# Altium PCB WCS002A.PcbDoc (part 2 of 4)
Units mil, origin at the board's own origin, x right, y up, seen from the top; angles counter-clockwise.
Board outline 2300 x 4058 mil, 4 copper layers (TOP, GND, PWR, BOTTOM), stack 28.8 mil thick; 311 components, 217 nets, 982 pads, 644 vias.
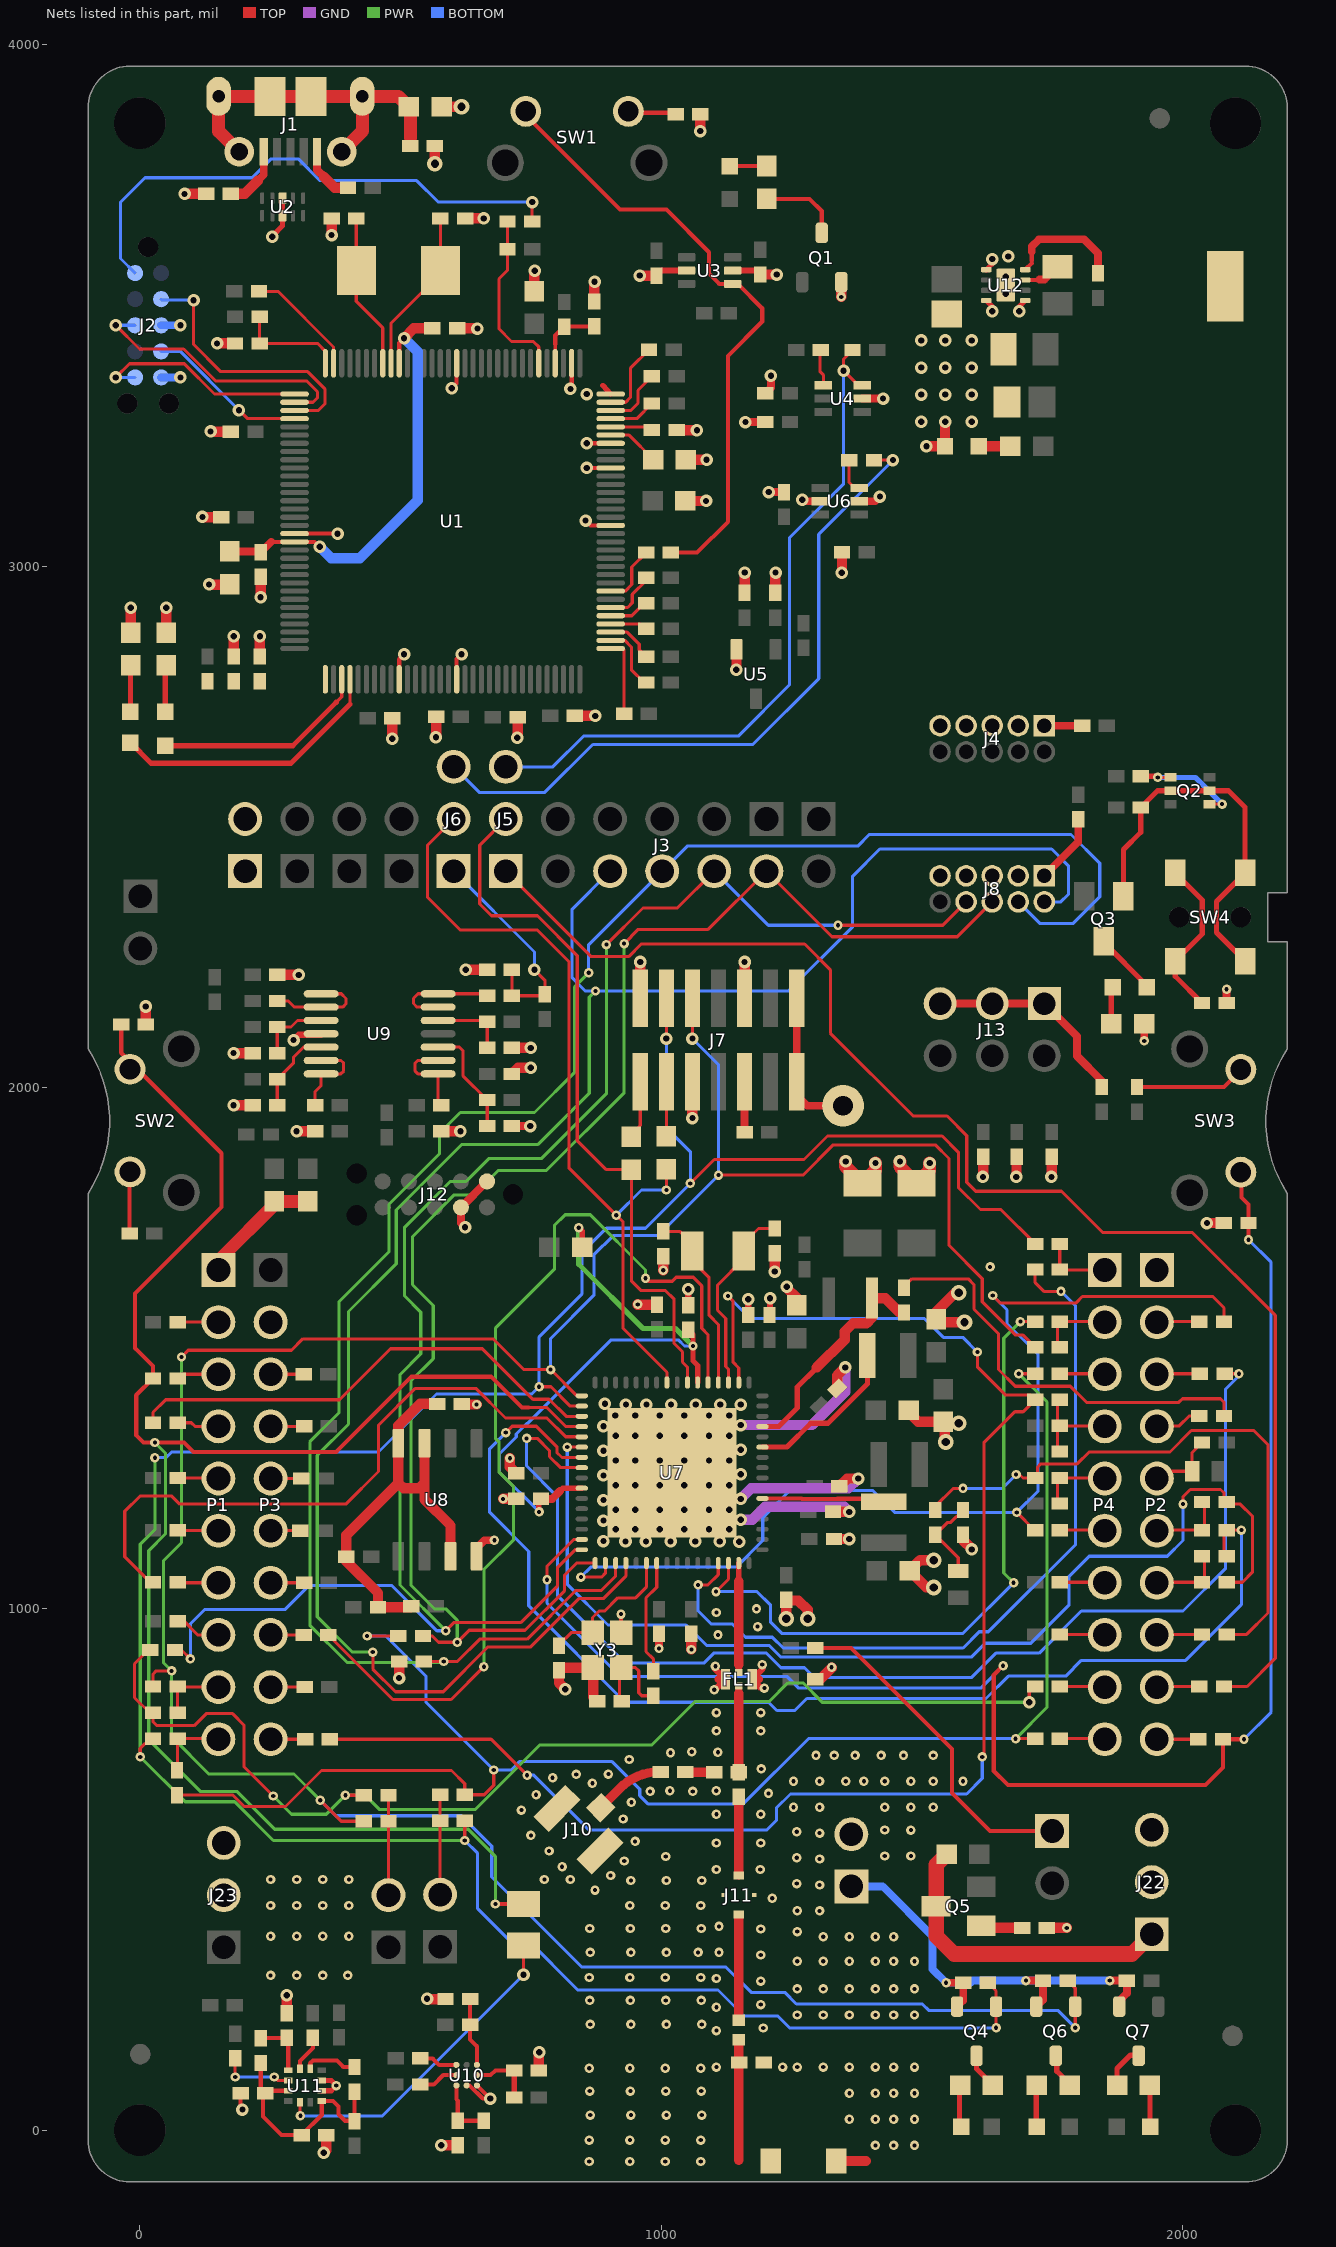
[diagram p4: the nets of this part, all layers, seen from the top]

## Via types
v1: diameter 18, hole 8, TOP to BOTTOM, tented both sides, 344 vias
v2: diameter 24, hole 12, TOP to BOTTOM, tented both sides, 244 vias
v3: diameter 24, hole 12.1, TOP to BOTTOM, 36 vias
v4: diameter 30, hole 16, TOP to BOTTOM, tented both sides, 18 vias
v5: diameter 24, hole 12.1, TOP to BOTTOM, tented top, 2 vias

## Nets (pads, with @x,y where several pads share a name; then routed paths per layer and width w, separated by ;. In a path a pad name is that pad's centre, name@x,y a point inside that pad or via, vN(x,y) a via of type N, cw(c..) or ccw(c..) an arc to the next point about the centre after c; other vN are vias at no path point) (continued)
FL_SWP: L7.2 R42.1 U7.45 | length 440.1
  TOP w10: U7.45@1194.02,1349.37 1225.28,1349.37 1260.79,1384.88 1260.79,1425.14 1298.43,1462.79
  TOP w19.9: 1298.43,1462.79 1351.79,1516.14 1351.79,1531.79 1367.79,1547.79 1393.79,1547.79 1404.13,1558.13 L7.2@1404.13,1595.79 1429.79,1595.79 1457.41,1568.17 R42.1@1465.79,1568.17
GND: C1.2 C2.2 C3.2 C4.2 C5.2 C6.1 C7.2 C8.2 C9.2 C10.2 C11.2 C12.2 C13.1 C14.2 C15.2 C16.2 C17.2 C18.2 C19.2 C20.2 C21.2 C22.2 C23.2 C24.2 C25.2 C27.2 C28.2 C29.2 C30.2 C31.2 C32.2 C33.2 C34.1 C34.2 C35.2 C36.2 C37.2 C38.2 C39.2 C40.2 C41.2 C42.2 C43.2 C44.2 C45.2 C46.2 C47.2 C48.2 C49.2 C50.2 C51.2 C52.2 C53.2 C54.2 C55.2 C56.2 C57.2 C58.2 C59.2 C60.2 C61.2 C62.2 C63.2 C64.2 D7.1 E1.1 E1.2 FL1.2 FL1.4 J2.3 J2.5 J4.3 J4.5 J4.7 J4.9 J7.5 J7.10 J7.13 J8.3 J8.5 J8.7 J8.9 J10.2 J10.3 J11.3 J11.4 J12.1 J12.9 J21.1 J21.2 J22.2 J22.3 J23.2 J23.3 J24.2 L2.2 L3.2 P2.1 P3.2 Q1.2 R11.1 R14.1 R16.1 R18.1 R19.1 R21.1 R23.1 R48.2 R49.2 R50.2 R51.2 R53.2 R106.1 R107.1 R114.1 R115.1 R126.1 R127.1 R128.1 R141.2 R142.2 R143.1 R144.1 R154.1 TP2.1 U1.10 U1.17 U1.48 U1.55 U1.58 U1.64 U1.66 U1.80 U1.114 U2.3 U2.8 U3.2 U3.5 U4.2 U5.2 U6.2 U6.5 U7.65 U8.4 U9.11 U10.A1 U10.A2 U11.8 U11.9 U12.1 U12.4 U12.5 U12.9 Y3.2 Y3.4 | length 6498.9
  TOP w7.5: U1.114@296.64,3062.17 v2(379.17,3062.17) ; v2(598.29,3340.79) 607.66,3350.16 U1.80@607.66,3388.94 ; U1.17@607.66,2782.64 607.66,2821.42 v2(617.03,2830.79) ; v2(854.79,3087.28) 864.16,3077.91 U1.48@902.94,3077.91
  TOP w8: C59.2@193.17,70.41 193.17,43.03 v2(196.79,39.41) ; U10.A2@626.79,85.72 632.28,85.72 657.59,60.41 v2(671.79,60.41) U10.A1@646.47,85.72 ; v2(856.88,3188.15) U1.55@902.94,3188.15 ; v2(856.88,3235.39) U1.58@902.94,3235.39 ; Y3.2@921.38,954.25 Y3.2@922.79,955.66 ; Y3.2@922.79,954.25 Y3.2@922.79,955.66 ; v1(922.79,989.79) Y3.2@922.79,955.66
  TOP w9: U1.10@497.43,2782.64 497.43,2821.42 v2(506.8,2830.79) ; v2(825.79,3339.79) 828.13,3342.13 U1.66@828.13,3388.94
  TOP w10: v2@254.29,3633.29 273.79,3652.79 U2.8@273.79,3672.06 U2.3@273.79,3705.52 ; U11.8@348.87,75.57 356.79,75.57 366.95,75.57 v1(376.79,85.41) 366.94,95.25 U11.9@348.87,95.25 ; 887.9,3346.1 U1.64@902.94,3329.96 ; U12.4@1623.39,3509.26 1634.79,3497.86 v2(1634.79,3488.79) ; U12.1@1623.39,3568.32 1634.79,3579.72 v2(1634.79,3588.79) ; v2(1686.79,3488.79) 1686.79,3497.86 U12.5@1698.19,3509.26
  TOP w12: v2(294.79,2090.79) 304.79,2100.79 U9.11@347.58,2100.79 ; C5.2@990.79,3557.17 1000.41,3566.79 U3.2@1048.5,3566.79 ; C28.2@1051.79,1582.41 v2(1051.79,1612.79) ; v1(1101.79,844.79) 1103.15,844.79 FL1.4@1123.15,864.79 1103.79,884.15 v1(1103.79,889.79) ; U3.5@1137.08,3566.79 1182.17,3566.79 C4.2@1189.79,3559.17 ; C46.2@1166.79,1563.41 v2(1166.79,1593.79) ; v1(1193.79,892.79) 1193.79,884.25 FL1.2@1174.33,864.79 1191.33,847.79 v1(1197.79,847.79) ; C36.2@1207.79,1563.41 1208.79,1564.41 v2(1208.79,1595.79)
  TOP w15: v2(623.79,1731.79) 615.79,1739.79 J12.9@615.79,1769.79 J12.1@665.79,1819.79 ; U8.4@645.79,1100.74 645.79,1115.99 661.1,1131.3 v1(679.9,1131.3) ; R114.1@713.41,1925.79 v2(748.79,1925.79) ; v1(995.79,923.79) C47.2@995.79,952.17 ; 1109.79,864.79 FL1.4@1123.15,864.79 ; v2(1161.39,3276.2) C14.2@1199.76,3276.2 ; FL1.2@1174.33,864.79 1187.79,864.79 ; C17.2@1199.76,3331.2 1210.39,3341.82 v2(1210.39,3365.2) ; v2(1206.39,3141.82) C24.2@1235.39,3141.82 ; v2(1270.39,3127.2) 1273.39,3124.2 U6.5@1304.98,3124.2 ; U6.2@1379.79,3124.2 1410.39,3124.2 v2(1419.39,3133.2) ; U4.2@1385.79,3321.2 v2(1425.39,3321.2) ; v1(1926.28,2089.28) R143.1@1926.28,2121.79 ; R144.1@2084.41,2161.79 v1(2084.41,2188.41)
  TOP w18: 1148.74,-58.07 L3.2@1148.74,172.5
  TOP w19.9: C53.2@263.41,2215.79 v2(304.79,2215.79) ; v2(624.79,2225.79) C54.2@666.17,2225.79 ; v1(696.79,1210.79) C32.2@722.17,1210.79 C32.2@726.5,1210.79 ; C50.2@803.79,882.17 803.79,857.79 v2(815.79,845.79) ; C50.2@803.79,886.5 Y3.4@868.23,886.5 ; Y3.4@869.37,886.5 869.37,831.2 877.17,823.41 C51.2@877.17,822.79 ; v1(1003.79,1649.12) C48.2@1003.79,1676.5 ; v1(1057.79,921.79) C38.2@1057.79,952.17 C38.2@1057.79,953.5 ; v2(1217.79,1646.79) C49.2@1217.79,1682.17 ; v2(1240.79,1617.79) 1240.79,1615.21 1259.79,1596.21 C45.2@1259.79,1582.28 ; C27.2@1295.41,864.79 1304.74,864.79 v1@1326.79,886.84 ; C29.2@1325.08,1185.79 C29.2@1329.41,1185.79 v2(1360.79,1185.79) ; C37.2@1331.41,1133.79 v2(1360.79,1133.79) ; C31.2@1334.43,1419.43 C31.2@1337.49,1422.49 1337.49,1447.49 v2(1352.79,1462.79) ; C30.2@1335.41,1235.79 C30.2@1337.56,1235.79 ; E1.2@1335.59,-59.21 1392.79,-59.21 ; C30.2@1341.41,1234.79 1356.41,1249.79 v2(1377.79,1249.79) ; v2@1509.77,3229.74 1509.82,3229.79 D7.1@1544.31,3229.79 v2@1544.29,3275 ; v4(1522.79,1040.79) 1508.28,1040.79 C35.2@1476.28,1072.79 1496.28,1092.79 v4(1522.79,1092.79) ; C40.2@1543.79,1355.29 1543.79,1321.79 v4(1545.79,1319.79) ; v4(1570.79,1605.79) 1563.79,1605.79 1527.79,1569.79 C42.2@1527.79,1555.28 1533.28,1549.79 v4(1581.79,1549.79) ; v2(2046.71,1739.79) R142.2@2079.17,1739.79
  TOP w20: R18.1@-17.21,2872.28 v2@-17.21,2919.79 ; R141.2@11.41,2120.79 v2(11.41,2155.17) ; R19.1@50.79,2872.28 v2@50.79,2919.79 ; v2(85.79,3713.79) L2.2@127.17,3713.79 ; v2@120.42,3093.79 C8.2@156.17,3093.79 ; v2@133.17,2964.28 C19.2@171.79,2964.28 ; v2@135.92,3257.79 C9.2@174.54,3257.79 ; v2(148,3427) C1.2@182.38,3427 ; v2(179.79,1965.79) R115.1@216.17,1965.79 ; v2(179.79,2065.79) R106.1@216.17,2065.79 ; R16.1@179.79,2826.41 v2@179.79,2865.03 ; C3.2@229.79,2826.41 v2@229.79,2865.03 ; v2@231.79,2940.54 C18.2@231.79,2979.17 ; R126.1@281.79,224.03 v2(281.79,258.79) ; v2(300.42,1915.79) C56.2@336.17,1915.79 ; v2(352.79,-43.59) 357.41,-38.97 C58.2@357.41,-9.59 ; v2(367.75,3634.8) C13.1@367.75,3666.61 ; v2@484.41,2669.17 C15.2@484.41,2707.79 ; v2@497.17,866.17 v2(497.17,866.98) R48.2@497.17,898.79 ; v2(550.79,251.79) 551.17,251.41 R127.1@586.17,251.41 ; v4(565.91,3771.91) C2.2@565.91,3805.79 ; v2@568.17,2672.17 C12.2@568.17,2710.79 ; v2@577.79,-29.59 578.17,-29.21 C57.2@609.79,-29.21 ; C55.2@578.41,1915.79 v2(614.79,1915.79) ; R14.1@578.78,3880.79 v4(616.79,3880.79) ; C20.2@608.41,3455.79 v2@647.03,3455.79 ; C33.2@617.28,1392.89 618.38,1391.79 v1(645.79,1391.79) ; C6.1@623.74,3666.7 v2(659.49,3666.7) ; v1(709.79,1288.79) 709.79,1272.17 C43.2@722.17,1259.79 ; C52.2@713.41,2025.79 725.41,2037.79 v2(749.79,2037.79) ; R107.1@713.41,2075.79 v2(749.79,2075.79) ; v2@724.41,2671.17 C16.2@724.41,2709.79 ; C10.2@756.79,3527.28 v2@756.79,3565.91 ; R128.1@765.41,114.41 765.41,149.03 v2(765.79,149.41) ; C7.2@834.41,2712.79 v2@873.03,2712.79 ; C23.2@871.79,3506.41 C23.2@871.79,3507.41 v2@871.79,3545.03 ; v1(954.79,1583.79) 955.17,1583.41 C44.2@991.79,1583.41 ; v2(958.98,3557.17) C5.2@990.79,3557.17 ; J7.13@959.79,2165.59 J7.13@959.79,2170.91 v2@959.79,2240.03 ; R11.1@1029.41,3260.79 v2@1068.03,3260.79 ; C11.2@1046.28,3124.79 v2(1085.97,3124.79) ; R23.1@1047.28,3203.79 v2(1086.97,3203.79) ; v2@1059.79,1941.55 J7.10@1059.79,2010.67 J7.10@1059.79,2015.98 ; v2(1075.03,3834.41) R21.1@1075.03,3866.79 ; v2@1144.39,2801.41 U5.2@1144.39,2840.03 ; J7.5@1159.79,2165.59 J7.5@1159.79,2170.91 v2@1159.79,2240.03 ; C21.2@1159.79,2948.41 v2@1159.79,2987.03 ; C4.2@1189.79,3559.17 v2(1221.6,3559.17) ; C22.2@1218.79,2948.41 v2@1218.79,2987.03 ; v4@1241.79,980.79 1239.79,982.79 C41.2@1239.79,1017.17 1241.17,1015.79 1262.79,1015.79 1280.79,997.79 v4(1280.79,980.79) ; v1(1345.19,3516.19) Q1.2@1345.19,3544.54 ; v2(1346.39,2987.2) 1346.76,2987.57 C25.2@1346.76,3026.2 ; C39.2@1477.28,1373.79 1492.78,1358.29 C40.2@1534.79,1358.29 ; C40.2@1543.79,1355.29 C40.2@1543.29,1355.79 ; v4(1570.79,1355.79) C40.2@1543.29,1355.79 ; R53.2@1578.79,1142.17 1578.79,1131.79 1595.79,1114.79 v2(1595.79,1113.79) ; v2@1617.41,1828.54 R51.2@1617.41,1867.17 ; v2@1681.41,1828.54 R50.2@1681.41,1867.17 ; R154.1@1739.41,387.79 v1(1777.79,387.79) ; v2@1748.79,1828.54 R49.2@1748.79,1867.17 ; C40.2@1534.79,1358.29 C40.2@1540.79,1358.29 C40.2@1543.29,1355.79 ; C40.2@1534.79,1358.29 1538.29,1354.79 1539.29,1355.79 C40.2@1543.29,1355.79
  TOP w25: v2(1353.79,1857.96) 1353.79,1847.87 C64.2@1385.79,1815.87 1410.79,1840.87 v2(1410.79,1854.96) ; v2(1457.79,1857.96) 1457.79,1847.87 C63.2@1489.79,1815.87 1514.79,1840.87 v2(1514.79,1854.96)
  GND w19.9: v2(1152.28,1170.91) 1174.91,1170.91 1199.74,1195.74 1350.84,1195.74 v2(1360.79,1185.79) ; v2(1152.49,1210.69) 1172.59,1230.79 1358.79,1230.79 v2(1377.79,1249.79) ; v2(1152.49,1352.42) 1289.04,1352.42 1352.79,1416.16 v2(1352.79,1462.79)
  BOTTOM w15: J2.5@40.79,3361.79 v2(77.79,3361.79) ; J2.3@40.79,3461.79 v2(77.79,3461.79)
  other v1: 861.79,-60.21 939.79,-60.21 1007.79,-60.21 1075.79,-60.21 1410.79,-29.21 1445.79,-29.21 1485.79,-29.21 861.79,-19.21 939.79,-19.21 1007.79,-19.21 1075.79,-19.21 1360.79,20.79 1410.79,20.79 1445.79,20.79 1485.79,20.79 863.79,28.79 941.79,28.79 1009.79,28.79 1077.79,28.79 1360.79,70.79 1410.79,70.79 1445.79,70.79 1485.79,70.79 862.79,74.79 940.79,74.79 1008.79,74.79 1076.79,74.79 861.79,118.79 939.79,118.79 1007.79,118.79 1075.79,118.79 1105.79,120.79 1232.79,120.79 1260.79,120.79 1310.79,120.79 1360.79,120.79 1410.79,120.79 1445.79,120.79 1485.79,120.79 1105.79,190.79 1195.79,195.79 863.79,202.79 941.79,202.79 1009.79,202.79 1077.79,202.79 1260.79,220.79 1310.79,220.79 1360.79,220.79 1410.79,220.79 1445.79,220.79 1485.79,220.79 1105.79,235.79 1190.79,240.79 862.79,248.79 940.79,248.79 1008.79,248.79 1076.79,248.79 1260.79,270.79 1310.79,270.79 1360.79,270.79 1410.79,270.79 1445.79,270.79 1485.79,270.79 1190.79,285.79 1105.79,290.79 861.79,292.79 939.79,292.79 1007.79,292.79 1075.79,292.79 250.79,296.79 300.79,296.79 350.79,296.79 398.79,296.79 1260.79,323.79 1310.79,323.79 1360.79,323.79 1410.79,323.79 1445.79,323.79 1485.79,323.79 1190.79,335.79 863.79,340.79 941.79,340.79 1009.79,340.79 1070.79,340.79 1110.79,340.79 1310.79,370.79 1360.79,370.79 1410.79,370.79 1445.79,370.79 250.79,371.79 300.79,371.79 350.79,371.79 400.79,371.79 1260.79,380.79 1190.79,385.79 862.79,386.79 940.79,386.79 1008.79,386.79 1076.79,386.79 1110.79,390.79 1260.79,420.79 1303.77,420.51 250.79,430.79 300.79,430.79 350.79,430.79 400.79,430.79 939.79,430.79 1007.79,430.79 1075.79,430.79 1212.79,444.79 872.89,460.27 1303.77,470.23 1259.79,472.79 941.79,478.79 1009.79,478.79 1077.79,478.79 250.79,480.79 300.79,480.79 350.79,480.79 400.79,480.79 775.79,480.79 825.79,480.79 902.89,488.27 1105.79,499.79 1189.79,499.79 809.89,505.27 928.89,516.27 1303.77,519.94 1259.79,522.51 1008.79,524.79 1428.77,525.82 1478.77,525.78 784.89,535.27 1105.79,550.79 1190.79,550.79 949.79,553.79 749.89,565.27 1303.77,569.66 1259.79,572.23 1428.77,575.54 1478.77,575.5 926.79,596.79 1105.79,605.79 1190.79,605.79 731.66,613.79 1253.77,619.38 1303.77,619.38 1428.77,619.42 1478.77,619.38 1521.75,619.38 942.66,628.79 759.89,643.27 1205.79,645.79 978.66,649.79 1060.28,649.69 1016.66,650.79 1105.66,650.79 867.89,665.27 1253.77,669.1 1303.77,669.1 1353.77,669.1 1388.77,669.1 1428.77,669.1 1478.77,669.1 1521.75,669.1 1578.77,669.1 791.66,675.79 836.89,682.27 898.66,682.79 1191.79,692.79 938.66,710.79 1296.75,718.82 1331.75,718.82 1371.75,718.82 1421.75,718.82 1464.73,718.82 1521.75,718.82 1017.66,723.79 1108.66,724.79 1058.66,725.79 1105.79,765.79 1190.79,765.79 1105.79,800.79 1190.79,800.79 1326.79,887.79 1108.79,949.79 1184.79,965.79 1105.79,992.79 1182.79,999.79 1630.79,1655.79
  other v2: 577.79,-29.21 931.44,1129.09 970.69,1129.09 1017.93,1129.09 1065.18,1129.09 1112.42,1129.09 1149.45,1128.55 889.09,1129.91 889.09,1169.16 889.09,1208.4 889.09,1255.64 1152.49,1257.93 889.09,1302.89 1152.49,1305.18 889.09,1350.13 932.27,1391.66 971.51,1391.66 1018.76,1391.66 1066,1391.66 1113.24,1391.66 1152.49,1391.66 892.03,1393.45 1617.03,1828.17 1681.03,1828.17 1748.41,1828.17 1059.79,1941.06 959.79,2240.51 1159.79,2240.51 484.03,2668.79 724.03,2670.79 567.79,2671.79 873.41,2712.41 1144.01,2801.03 180.17,2865.41 230.17,2865.41 -17.59,2920.17 50.41,2920.17 231.41,2940.17 132.79,2964.66 1160.17,2987.41 1219.17,2987.41 120.04,3094.17 1508.56,3229.79 135.54,3258.17 1068.41,3260.41 1498.79,3276.79 1544.79,3276.79 1595.79,3276.79 1498.79,3328.79 1544.79,3328.79 1595.79,3328.79 856.88,3329.88 1498.79,3380.79 1544.79,3380.79 1595.79,3380.79 1498.79,3432.79 1544.79,3432.79 1595.79,3432.79 647.41,3455.41 872.17,3545.41 757.17,3566.28 1665.79,3593.79 253.79,3631.79
  other v3: 912.68,1152.68 949.92,1152.68 997.17,1152.68 1044.41,1152.68 1091.65,1152.68 1130.69,1152.68 912.68,1189.92 949.92,1189.92 997.17,1189.92 1044.41,1189.92 1091.65,1189.92 1130.69,1189.92 912.68,1237.17 949.92,1237.17 997.17,1237.17 1044.41,1237.17 1091.65,1237.17 1130.69,1237.17 912.68,1284.41 949.92,1284.41 997.17,1284.41 1044.41,1284.41 1091.65,1284.41 1130.69,1284.41 912.68,1331.65 949.92,1331.65 997.17,1331.65 1044.41,1331.65 1091.65,1331.65 1130.69,1331.65 911.69,1370.69 949.92,1370.69 997.17,1370.69 1044.41,1370.69 1091.65,1370.69 1130.69,1370.69
  other v4: 1239.79,980.79
  other v5: 1660.6,3522.3 1660.79,3555
IRSTN: J2.10 R22.1 | length 1043.4
  TOP w6: R22.1@752.41,3660.79 v2(752.41,3698.17)
  BOTTOM w6: J2.10@-9.21,3561.79 -37.21,3589.79 -37.21,3697.79 9.79,3744.79 215.79,3744.79 252,3781 303.8,3781 345.5,3739.3 530.8,3739.3 571.93,3698.17 v2(752.41,3698.17)
ITCK: J2.4 U1.100 | length 309.3
  TOP w6: v2(190,3299) 190.57,3299 206.94,3282.64 U1.100@296.64,3282.64
  BOTTOM w6: J2.4@40.79,3411.79 77.21,3411.79 v2(190,3299)
ITDI: J2.8 U1.98 | length 535.9
  TOP w6: v2(-46.21,3461.79) -0.63,3416.2 83.8,3416.2 145.21,3354.79 319.99,3354.79 340.79,3333.99 340.79,3322.79 332.13,3314.13 U1.98@296.64,3314.13
  BOTTOM w6: v2(-46.21,3461.79) J2.8@-9.21,3461.79
ITDO: J2.6 U1.97 | length 412.4
  TOP w6: v2(-46.21,3361.79) -20,3388 85,3388 143.12,3329.88 U1.97@294.29,3329.88
  BOTTOM w6: v2(-46.21,3361.79) J2.6@-9.21,3361.79
ITMS: J2.2 U1.99 | length 527.3
  TOP w6: v2(103,3510) 103,3425 155.21,3372.79 321.79,3372.79 354.79,3339.79 354.79,3310.79 342.39,3298.39 U1.99@296.64,3298.39
  BOTTOM w6: J2.2@40.79,3511.79 42.57,3510 v2(103,3510)
LED0: D2.2 U1.3 | length 412.2
  TOP w6: 375.79,2737.79 387.19,2749.19 U1.3@387.19,2782.64
  TOP w10: D2.2@48.79,2655.31 293.31,2655.31 376.79,2738.79
LED1: D1.1 U1.4 | length 532.1
  TOP w6: 402.94,2734.94 U1.4@402.94,2782.64
  TOP w10: D1.1@-18.21,2661.26 21.26,2621.79 289.79,2621.79 402.94,2734.94
LP_GPIO_01: J5.1 R82.2 | length 2751
  TOP w6: J5.1@701.79,2414.79 865.79,2250.79 937.54,2250.79 961.75,2275 1275,2275 1324.5,2225.5 1324.5,2104.07 1483.37,1945.2 1548.37,1945.2 1586,1907.57 1586,1818 1603.21,1800.79 1767.79,1800.79 1846.79,1721.79 2018.79,1721.79 2177.79,1562.79 2177.79,904.79 2123.79,850.79 R82.2@2079.68,850.79
LP_GPIO_02: C54.1 J6.1 R101.2 R105.2 | length 423.3
  TOP w6: C54.1@713.41,2225.79 R105.2@713.41,2175.79 774.17,2175.79 R101.2@776.79,2178.41 776.79,2205.79 v2(756.79,2225.79)
  BOTTOM w6: J6.1@601.79,2414.79 756.79,2259.79 v2(756.79,2225.79)
LP_RESET_OUT: D5.2 P2.5 R136.2 | length 134.8
  TOP w6: P2.5@1952.06,1249.78 1966.06,1263.79 D5.2@2018.2,1263.79 2018.2,1299.82 R136.2@2037.17,1318.79
NetC1_1: C1.1 R13.2 U1.96 | length 206.3
  TOP w6: R13.2@229.62,3478 C1.1@229.62,3427 340.57,3427 355.69,3411.88 U1.96@355.69,3388.94
NetC2_1: C2.1 J1.6 J1.7 J1.8 J1.9 J1.10 J1.11 R14.2 | length 694.7
  TOP w22: C2.1@518.66,3805.79 518.66,3820.66
  TOP w25: J1.10@190.36,3794.64 151.21,3833.79 150.99,3833.79 J1.9@150.99,3900.94 J1.8@249.42,3900.94 J1.7@328.16,3900.94 J1.6@426.58,3900.94 ; J1.11@387.21,3794.64 426.58,3834.01 J1.6@426.58,3900.94 ; 518.66,3820.66 518.66,3877.91 R14.2@515.79,3880.79 495.64,3900.94 J1.6@426.58,3900.94
NetC3_1: C3.1 R15.2 R16.2 U1.1
NetC6_2: C6.2 U1.88 Y1.2 | length 317
  TOP w6: U1.88@481.68,3388.94 481.68,3465.68 576.5,3560.5 Y1.2@576.5,3566.79 C6.2@576.5,3666.7
NetC13_2: C13.2 U1.89 Y1.1 | length 298.8
  TOP w6: C13.2@415.08,3666.7 Y1.1@415.08,3566.79 415.08,3507.64 465.93,3456.79 U1.89@465.93,3388.94
NetC18_1: C18.1 C19.1 C20.1 U1.87 U1.115 | length 858.7
  TOP w7.5: 252.04,3046.42 U1.115@296.64,3046.42 335.42,3046.42 v2(344.79,3037.05)
  TOP w9: U1.87@497.43,3388.94 497.43,3427.72 v2(506.8,3437.09)
  TOP w15: C19.1@177.79,3030.29 179.91,3028.17 233.54,3028.17 251.8,3046.42 252.04,3046.42
  TOP w20: v2(506.8,3437.09) 525.5,3455.79 C20.1@561.17,3455.79
  BOTTOM w20: v2(344.79,3037.05) 367.05,3014.79 421.79,3014.79 532.79,3125.79 532.79,3411.09 v2(506.8,3437.09)
NetC23_1: C23.1 R28.2 U1.68 | length 135.3
  TOP w7.5: U1.68@796.64,3388.94 796.64,3425.64
  TOP w8: 796.64,3425.64 796.64,3442.02 R28.2@813.79,3459.17 C23.1@871.79,3459.17
NetC26_1: C26.1 R37.2 | length 55.5
  TOP w18: C26.1@1046.03,686.41 R37.2@1101.54,686.41
NetC26_2: C26.2 J10.1 | length 136.9
  TOP w18: J10.1@883.89,618.71 920.82,655.64 cw(c998.2,578.25) C26.2@984.56,686.84 ; C26.2@986.38,687.05 C26.2@998.78,687.05
NetC28_1: C28.1 C32.1 R36.1 U7.10 U7.54 | length 1231.8
  TOP w10: C32.1@765.08,1210.79 765.08,1186.5 v1(765.79,1185.79) ; 805.79,1225.79 811.26,1231.26 U7.10@847.56,1231.26 ; v1(841.79,1730.79) 848.28,1724.29 R36.1@848.28,1693.79 ; C28.1@1051.79,1535.17 1060.79,1526.17 1060.79,1475.67 1070,1466.46 U7.54@1070,1434.02
  TOP w15: C32.1@765.08,1210.79 C32.1@769.41,1210.79 790.79,1210.79 805.79,1225.79
  PWR w10: v1(841.79,1730.79) 841.79,1660.79 964.79,1537.79 1027.21,1537.79 v1(1061,1504)
  BOTTOM w6: v1(765.79,1185.79) 689.79,1261.79 689.79,1297.5 721.79,1329.5 721.79,1335.07 741.5,1354.79 742.87,1354.79 903.87,1515.79 1032.79,1515.79 1044.57,1504 v1(1061,1504)
NetC33_1: C33.1 R38.1 R39.1 R41.1 U8.3 U8.7 U8.8 | length 836.9
  TOP w19.9: R39.1@519.54,1005.79 R39.1@520.54,1004.79 518.54,1002.79 R38.1@456.71,1002.79 456.71,1030.29 396.79,1090.21 396.79,1090.79 396.17,1091.41 R41.1@396.17,1099.79 395.79,1100.17 395.79,1130.22 396.11,1130.54 396.11,1141.11 495.79,1240.79 ; U8.7@545.79,1307.28 545.79,1240.79 ; C33.1@566.5,1392.89 537.89,1392.89 495.79,1350.79 495.79,1240.79 ; U8.3@595.79,1118.3 595.79,1159.79 545.79,1209.79 545.79,1240.79 ; 495.79,1240.79 505.79,1230.79 535.79,1230.79 545.79,1240.79
NetC48_1: C48.1 U7.52 Y2.2 | length 352.2
  TOP w6: C48.1@1003.79,1723.74 1035.26,1723.74 1059.57,1699.43 Y2.2@1059.57,1685.79 1059.57,1667 1091.79,1634.79 1091.79,1562.79 1109.79,1544.79 1109.79,1434.41 U7.52@1109.37,1434.02
NetC49_1: C49.1 U7.51 Y2.1 | length 368.2
  TOP w6: U7.51@1129.05,1434.02 1129.08,1459.49 1123.79,1464.79 1123.79,1556.79 1107.79,1572.79 1107.79,1620.79 1158,1671 1158,1701 1186.41,1729.41 C49.1@1217.79,1729.41
NetC50_1: C50.1 U7.22 Y3.3 | length 278
  TOP w6: C50.1@803.79,929.41 803.79,930.79 827.25,954.25 Y3.3@868.23,954.25 868.23,983.23 880.79,995.79 891.79,995.79 916.79,1020.79 950.79,1020.79 971.58,1041.58 U7.22@971.57,1087.56
NetC51_1: C51.1 R44.1 Y3.1 | length 180
  TOP w6: C51.1@920.08,817.79 Y3.1@920.08,886.02 ; Y3.1@920.08,887.32 950.25,887.32 956.81,880.76 956.81,838.76 962.41,833.17 R44.1@984.79,833.17
NetC57_1: C57.1 R116.1 U10.A3 | length 118.5
  TOP w8: U10.A3@607.1,85.72 607.1,59.09 609.79,56.41 C57.1@609.79,18.03 659.01,18.03 R116.1@659.31,18.34
NetC58_1: C58.1 C59.1 R117.1 R122.2 R132.2 U11.3 U11.7 | length 468
  TOP w8: R122.2@231.79,128.79 231.79,79.03 C59.1@240.41,70.41 ; U11.3@284.7,75.57 245.57,75.57 C59.1@240.41,70.41 ; R132.2@411.79,73.79 411.79,18.03 393.17,18.03 380.79,30.41 380.79,45.41 370.31,55.88 U11.7@348.87,55.88 348.87,29.12 C58.1@310.17,-9.59 271.79,-9.59 236.08,26.12 236.08,66.08 C59.1@240.41,70.41
NetD1_2: D1.2 R18.2 | length 89.4
  TOP w10: D1.2@-18.21,2720.31 -18.21,2808.29 R18.2@-17.21,2809.29
NetD2_1: D2.1 R19.2 | length 89.9
  TOP w10: D2.1@48.79,2720.27 48.79,2807.29 R19.2@50.79,2809.29
NetD3_1: D3.1 R24.2 | length 71
  TOP w8: D3.1@1131.79,3766.98 R24.2@1202.79,3766.98
NetD4_1: D4.1 R52.1 R53.1 | length 160.6
  TOP w6: D4.1@1569.79,1072.38 1569.79,1098.17 R52.1@1525.79,1142.17 1549.41,1165.79 1555.17,1165.79 R53.1@1578.79,1189.41
NetD6_1: D6.1 R143.2 | length 71.2
  TOP w10: R143.2@1863.29,2121.79 1863.29,2188.77 D6.1@1866.31,2191.79
NetD6_2: D6.2 Q3.3 | length 122.5
  TOP w10: Q3.3@1848.99,2280.21 1848.99,2277.81 1931.27,2195.53 D6.2@1931.27,2191.79
NetD7_2: D7.2 R145.2 | length 49.5
  TOP w20: D7.2@1610.27,3229.79 R145.2@1659.8,3229.79
NetD8_2: D8.2 R148.2 | length 88
  TOP w10: D8.2@1572.29,6.79 R148.2@1572.29,94.79
NetD9_1: D9.1 R147.2 | length 88
  TOP w10: D9.1@1719.29,6.79 R147.2@1719.29,94.79
NetD10_1: D10.1 R149.2 | length 88.4
  TOP w10: R149.2@1937.28,94.79 1937.28,7.79 D10.1@1938.27,6.79
NetFL1_1: FL1.1 U7.31 | length 209.9
  TOP w10: 1148.74,1052.79 U7.31@1148.74,1083.62 ; U7.31@1148.77,1083.65 U7.31@1148.74,1087.56
  TOP w12: FL1.1@1148.74,877.58 1148.74,892.79
  TOP w18: 1148.74,892.79 1148.74,1052.79
NetFL1_3: FL1.3 R37.1 R40.1 | length 164
  TOP w12: 1148.74,837.79 FL1.3@1148.74,851.99
  TOP w18: R37.1@1148.74,688.03 1148.74,837.79
NetJ1_1: J1.1 L1.1 | length 106.2
  TOP w15.75: J1.1@339.97,3792.64 339.97,3759.61 353.79,3745.79
  TOP w20: 353.79,3745.79 373.79,3725.79 L1.1@399.17,3725.79
NetJ1_5: J1.5 L2.1 | length 120.5
  TOP w15: 225.79,3738.79 237.43,3750.43 ; J1.5@237.43,3792.46 237.43,3750.43 ; 237.61,3750.61 237.43,3750.43
  TOP w19.9: L2.1@174.41,3713.79 200.79,3713.79 225.79,3738.79
NetJ4_1: J4.1 R29.2 | length 72.4
  TOP w15: J4.1@1734.79,2693.79 R29.2@1807.17,2693.79
NetJ5_3: J5.3 R26.2 U4.3 | length 1348.8
  TOP w6: R26.2@1366.49,3413.92 1349.79,3397.22 v2(1349.79,3374.79) 1377.79,3346.79 U4.3@1385.79,3346.79
  BOTTOM w6: J5.3@701.79,2614.79 791.79,2614.79 850.79,2673.79 1147.79,2673.79 1245.79,2771.79 1245.79,3053.79 1349.79,3157.79 v2(1349.79,3374.79)
NetJ6_3: J6.3 R31.1 | length 1325.4
  TOP w6: R31.1@1408.01,3203.2 v2(1444.39,3203.2)
  BOTTOM w6: J6.3@601.79,2614.79 650.79,2565.79 776.79,2565.79 868.79,2657.79 1175.79,2657.79 1302,2784 1302,3060.81 v2(1444.39,3203.2)
NetJ7_1: J7.1 J7.2 TP1.1 | length 277.8
  TOP w15: J7.1@1259.79,2165.59 1259.79,1985.21 1280.21,1964.79 TP1.1@1348.79,1964.79
NetJ7_6: J7.6 R30.1 | length 101.8
  TOP w15: R30.1@1159.79,1914.17 J7.6@1159.79,2015.98
NetJ7_12: J7.12 R33.2 | length 109.7
  TOP w6: R33.2@1009.79,1906.28 J7.12@1009.79,2015.98
NetJ7_14: J7.14 R34.2 | length 116.9
  TOP w6: R34.2@944.79,1905.28 944.79,1911.79 959.79,1926.79 J7.14@959.79,2015.98
NetJ8_1: J8.1 R32.2 | length 135.4
  TOP w15: J8.1@1734.79,2405.79 1799.91,2470.91 R32.2@1799.91,2514.17
NetJ9_1: J9.1 R35.1 | length 649
  TOP w8: R35.1@1295.41,924.79 1363.79,924.79 1557.77,730.81 1557.77,646.81 1630.79,573.79 J9.1@1749.79,573.79
NetJ11_1: J11.1 R40.2 | length 149
  TOP w18: J11.1@1148.74,490.16 R40.2@1148.79,639.17
NetJ11_2: J11.2 L3.1 | length 200.3
  TOP w18: L3.1@1148.74,211.08 J11.2@1148.74,411.42
NetJ13_1: J13.1 J13.3 J13.5 R47.2 | length 405.6
  TOP w15: J13.5@1534.79,2160.79 J13.3@1634.79,2160.79 J13.1@1734.79,2160.79 1797.4,2098.17 1797.4,2060.3 1844.8,2012.9 R47.2@1844.8,2000.79
NetJ15_2: J15.2 R123.2 R124.2 | length 191.5
  TOP w6: J15.2@476.79,450.79 R123.2@476.79,592.31 R124.2@476.79,642.31
NetJ16_2: J16.2 R129.2 R131.2 | length 191.5
  TOP w6: J16.2@575.79,451.79 R129.2@575.79,593.31 R131.2@575.79,643.31
NetJ22_1: J22.1 Q5.3 R150.1 | length 608.4
  TOP w30: R150.1@1547.29,528.79 1527.17,508.67 Q5.3@1527.17,429.39 1527.17,372.4 1561.79,337.79 1902.79,337.79 J22.1@1940.79,375.79
NetJ24_1: J24.1 Q4.2 Q6.2 Q7.2 R151.2 R152.2 R153.2 | length 870.6
  TOP w15: v1(1546.42,282.79) R151.2@1579.17,282.79 1579.17,248.81 Q4.2@1567.39,237.03 ; v1(1699.42,286.79) R152.2@1732.17,286.79 1732.17,249.81 Q6.2@1719.39,237.03 ; v1(1860.42,286.79) R153.2@1893.17,286.79 1893.17,262.47 1878.39,247.69 Q7.2@1878.39,237.03
  BOTTOM w15: J24.1@1364.6,467.5 1424.6,467.5 1520.4,371.7 1520.4,308.8 v1(1546.42,282.79) 1593.69,282.79 1597.69,286.79 v1(1699.42,286.79) v1(1860.42,286.79)
NetL4_2: L4.2 U7.38 | length 235.6
  TOP w8: U7.38@1194.02,1211.57 1269.33,1211.58 1270.11,1210.8 1337.61,1210.8 1337.79,1210.98 1420.97,1210.98 L4.2@1426.79,1205.16
NetL6_2: L6.2 U7.43 | length 306.1
  TOP w10: U7.43@1194.02,1310 1241,1310 1286.79,1355.79 1319.79,1355.79 1395.42,1431.42 L6.2@1395.42,1485.79
NetL8_1: L8.1 U12.7 | length 68.6
  TOP w8: U12.7@1698.19,3548.63 1722.63,3548.63
  TOP w15: 1725.79,3549.79 1735.35,3549.79 L8.1@1759.79,3574.22
NetP1_1: P1.1 R56.2 R57.2 | length 236.5
  TOP w25: P1.1@149.79,1649.79 149.79,1666.89 264.19,1781.29 R56.2@321.79,1781.29
NetP1_2: P1.2 R65.2 | length 77.4
  TOP w6: R65.2@72.41,1549.79 P1.2@149.79,1549.79
NetP1_3: P1.3 R67.2 | length 80.7
  TOP w6: R67.2@72.41,1441.79 80.41,1449.79 P1.3@149.79,1449.79
NetP1_4: P1.4 R71.2 | length 80.3
  TOP w6: R71.2@72.41,1356.79 98.61,1356.79 105.61,1349.79 P1.4@149.79,1349.79
NetP1_5: P1.5 R75.2 | length 77.8
  TOP w6: R75.2@72.41,1250.79 148.79,1250.79 P1.5@149.79,1249.79
NetP1_6: P1.6 R79.2 | length 72.8
  TOP w6: R79.2@77.41,1150.79 78.41,1149.79 P1.6@149.79,1149.79
NetP1_7: P1.7 R83.2 | length 72.8
  TOP w6: R83.2@77.41,1050.79 78.41,1049.79 P1.7@149.79,1049.79
NetP1_8: P1.8 R87.2 | length 88.1
  TOP w6: R87.2@72.41,975.79 84.79,975.79 110.79,949.79 P1.8@149.79,949.79
NetP1_9: P1.9 R89.2 R95.2 | length 127.8
  TOP w6: R95.2@72.41,800.79 R89.2@72.41,850.79 73.41,849.79 P1.9@149.79,849.79
NetP1_10: P1.10 R91.2 R96.2 | length 137.6
  TOP w6: R96.2@71.19,689.92 72.41,691.14 R91.2@72.41,750.79 145.79,750.79 P1.10@147.79,748.79
NetP2_2: P2.2 R60.1 | length 91.1
  TOP w6: P2.2@1950.79,1550.79 R60.1@2041.89,1550.79
NetP2_3: P2.3 R62.1 | length 92.2
  TOP w6: P2.3@1950.79,1450.79 R62.1@2042.97,1450.79
NetP2_4: P2.4 R64.1 | length 88.2
  TOP w6: P2.4@1950.79,1350.79 1993.79,1350.79 2012.79,1369.79 R64.1@2031.07,1369.79
NetP2_6: P2.6 R70.1 R97.1 | length 141.1
  TOP w6: P2.6@1950.79,1150.79 2041.89,1150.79 R97.1@2041.89,1200.79
NetP2_7: P2.7 R74.1 R99.1 | length 141.1
  TOP w6: P2.7@1950.79,1050.79 2041.89,1050.79 R99.1@2041.89,1100.79
NetP2_8: P2.8 R78.1 | length 91.1
  TOP w6: P2.8@1950.79,950.79 R78.1@2041.89,950.79
NetP2_9: P2.9 R82.1 | length 91.1
  TOP w6: P2.9@1950.79,850.79 R82.1@2041.89,850.79
NetP2_10: P2.10 R86.1 | length 78.1
  TOP w6: P2.10@1952.06,749.78 R86.1@2030.17,749.78
NetP3_3: P3.3 R68.1 | length 64.2
  TOP w6: P3.3@249.96,1449.79 P3.3@250.7,1449.79 R68.1@314.17,1449.79
NetP3_4: P3.4 R72.1 | length 65.2
  TOP w6: P3.4@249.96,1349.79 P3.4@250.7,1349.79 R72.1@315.17,1349.79
NetP3_5: P3.5 R76.1 | length 59.3
  TOP w6: P3.5@249.97,1249.8 R76.1@309.28,1249.8
NetP3_6: P3.6 R80.1 | length 58
  TOP w6: P3.6@249.96,1149.79 250.07,1149.9 R80.1@307.88,1149.9
NetP3_7: P3.7 R84.1 | length 65.2
  TOP w6: P3.7@249.96,1049.79 P3.7@250.7,1049.79 R84.1@315.17,1049.79
NetP3_8: P3.8 R88.1 | length 64.2
  TOP w6: P3.8@249.96,949.79 P3.8@250.7,949.79 R88.1@314.17,949.79
NetP3_9: P3.9 R90.1 | length 66.2
  TOP w6: P3.9@249.96,849.79 P3.9@250.7,849.79 R90.1@316.17,849.79
NetP3_10: P3.10 R92.1 | length 67.2
  TOP w6: P3.10@249.96,749.79 P3.10@250.7,749.79 R92.1@317.17,749.79
NetP4_1: P4.1 R54.2 R58.2 | length 136.4
  TOP w6: R58.2@1764.41,1699.79 R54.2@1764.41,1650.79 1765.41,1649.78 P4.1@1850.7,1649.78 P4.1@1851.44,1649.78
NetP4_2: P4.2 R55.2 R59.2 | length 136.1
  TOP w6: R59.2@1759.68,1505.79 1759.68,1550.79 R55.2@1764.41,1550.79 P4.2@1850.79,1550.79
NetP4_3: P4.3 R61.2 | length 91.1
  TOP w6: R61.2@1759.68,1450.79 R61.2@1764.41,1450.79 P4.3@1850.79,1450.79
NetP4_4: P4.4 R63.2 R93.2 R94.2 | length 190.1
  TOP w6: R94.2@1759.68,1301.79 R63.2@1759.68,1350.79 ; R93.2@1759.68,1400.79 R63.2@1759.68,1350.79 ; P4.4@1850.79,1350.79 R63.2@1764.41,1350.79 R63.2@1759.68,1350.79
NetP4_5: P4.5 R66.2 R98.2 | length 131.1
  TOP w6: R98.2@1759.68,1210.79 1759.68,1250.79 R66.2@1764.41,1250.79 P4.5@1850.79,1250.79
NetP4_6: P4.6 R69.2 | length 91.1
  TOP w6: R69.2@1759.68,1150.79 R69.2@1764.41,1150.79 P4.6@1850.79,1150.79
NetP4_7: P4.7 R73.2 | length 91.1
  TOP w6: R73.2@1759.68,1050.79 R73.2@1764.41,1050.79 P4.7@1850.79,1050.79
NetP4_8: P4.8 R77.2 | length 91.1
  TOP w6: R77.2@1759.68,950.79 R77.2@1764.41,950.79 P4.8@1850.79,950.79
NetP4_9: P4.9 R81.2 | length 91.1
  TOP w6: R81.2@1759.68,850.79 R81.2@1764.41,850.79 P4.9@1850.79,850.79
NetP4_10: P4.10 R85.2 | length 91.1
  TOP w6: R85.2@1759.68,750.79 R85.2@1764.41,750.79 P4.10@1850.79,750.79
NetQ1_3: Q1.3 R24.1 | length 156.5
  TOP w8: R24.1@1202.79,3704.29 1284.28,3704.29 1307.79,3680.79 Q1.3@1307.79,3639.03
NetQ2_1: Q2.1 Q2.4 R137.1 | length 226.9
  TOP w6: v1(1952.37,2594.58) Q2.1@1976.69,2594.58 ; Q2.4@2051.49,2543.4 v1(2075.81,2543.4)
  TOP w10: R137.1@1919.71,2596.99 1949.96,2596.99 v1(1952.37,2594.58)
  BOTTOM w10: v1(1952.37,2594.58) 2024.63,2594.58 v1(2075.81,2543.4)
NetQ2_2: Q2.2 Q2.5 Q3.1 R140.1 SW4.3 SW4.4 | length 751.1
  TOP w10: Q3.1@1886.39,2366.82 1886.39,2456.05 1919.71,2489.37 R140.1@1919.71,2536.99 1951.71,2568.99 Q2.2@1976.69,2568.99 Q2.5@2051.49,2568.99 2088.09,2568.99 2119.72,2537.36 SW4.4@2119.72,2411.43 2064.79,2356.5 2064.79,2297.07 SW4.3@2119.72,2242.14
NetQ4_3: Q4.3 R148.1 | length 69.8
  TOP w10: Q4.3@1604.79,142.54 1604.79,117.79 1636.28,86.29 R148.1@1636.28,85.79
NetQ5_1: Q5.1 R154.2 | length 80.1
  TOP w20: Q5.1@1613.79,391.98 1617.98,387.79 R154.2@1692.17,387.79
NetQ6_3: Q6.3 R147.1 | length 70.6
  TOP w10: Q6.3@1758.79,146.29 1758.79,112.79 1783.28,88.29 R147.1@1783.28,85.79
NetQ7_3: Q7.3 R149.1 | length 86.1
  TOP w10: R149.1@1874.29,85.79 1874.29,118.29 1899.78,143.78 Q7.3@1917.28,143.78
NetR1_2: R1.2 U1.33 | length 149.1
  TOP w6: U1.33@902.94,2841.69 925.88,2841.69 928.79,2838.79 R1.2@928.79,2716.79
NetR2_2: R2.2 U1.34 | length 110.4
  TOP w6: U1.34@919.79,2857.44 929.93,2857.44 942.79,2844.59 942.79,2800.79 966.79,2776.79 R2.2@971.17,2776.79
NetR3_2: R3.2 U1.35 | length 94.2
  TOP w6: U1.35@902.94,2873.19 934.65,2873.19 957.79,2850.05 957.79,2839.17 R3.2@971.17,2825.79
NetR4_2: R4.2 U1.36 | length 73.3
  TOP w6: U1.36@902.94,2888.94 959.02,2888.94 R4.2@971.17,2876.79
NetR5_2: R5.2 U1.37 | length 77
  TOP w6: U1.37@902.94,2904.68 943.68,2904.68 964.79,2925.79 R5.2@971.17,2925.79
NetR6_2: R6.2 U1.38 | length 104.7
  TOP w6: U1.38@902.94,2920.43 935.43,2920.43 944.42,2929.42 944.42,2945.62 971.17,2972.37 R6.2@971.17,2977.79
NetR7_2: R7.2 U1.63 | length 148
  TOP w6: U1.63@902.94,3314.13 931.76,3314.13 940.79,3323.16 940.79,3379.03 R7.2@976.54,3414.79
NetR8_1: R8.1 SW1.2 U3.4 | length 1201.4
  TOP w8: SW1.2@740.36,3864.3 920.87,3683.79 1009.79,3683.79 1091.79,3601.79 1091.79,3560.79 1111.38,3541.2 U3.4@1137.08,3541.2 1146.9,3541.2 1193.79,3494.31 1193.79,3468.79 1127.79,3402.79 1127.79,3084.79 1068.79,3025.79 R8.1@1018.41,3025.79
NetR8_2: R8.2 U1.40 | length 118.5
  TOP w6: U1.40@902.94,2951.93 930.93,2951.93 943.5,2964.5 943.5,2998.12 R8.2@971.17,3025.79
NetR9_2: R9.2 U1.62 | length 120.7
  TOP w6: U1.62@902.94,3298.39 941.39,3298.39 955.42,3312.42 955.42,3337.04 R9.2@982.17,3363.79
NetR10_2: R10.2 U1.61 | length 91.3
  TOP w6: U1.61@902.94,3282.64 953.02,3282.64 R10.2@982.17,3311.79
NetR11_2: R11.2 U1.60 | length 81.8
  TOP w6: U1.60@902.94,3266.89 976.06,3266.89 R11.2@982.17,3260.79
NetR12_2: R12.2 U1.95 | length 218.4
  TOP w6: R12.2@228.41,3526.79 264.79,3526.79 371.44,3420.13 U1.95@371.44,3388.94
NetR20_2: R20.2 R22.2 U1.70 | length 334.9
  TOP w6: R22.2@705.17,3660.79 R20.2@705.17,3607.79 705.17,3567.17 688.79,3550.79 688.79,3454.79 712.79,3430.79 754.79,3430.79 765.14,3420.43 U1.70@765.14,3388.94
NetR21_2: R21.2 SW1.1 | length 91.6
  TOP w8: SW1.1@937.21,3869.3 1025.28,3869.3 R21.2@1027.79,3866.79
NetR23_2: R23.2 U1.59 | length 101.8
  TOP w6: U1.59@902.94,3251.14 938.43,3251.14 984.29,3205.28 R23.2@984.29,3203.79
NetR27_1: R27.1 U4.4 | length 66.4
  TOP w6: R27.1@1304.28,3410.38 1304.28,3373.3 1310.98,3366.6 U4.4@1310.98,3346.79
NetR31_2: R31.2 U6.3 | length 66.9
  TOP w6: R31.2@1360.76,3203.2 1360.39,3202.82 1360.39,3160.2 1370.8,3149.79 U6.3@1379.79,3149.79
NetR44_2: R44.2 U7.23 | length 221.4
  TOP w6: R44.2@984.79,880.41 984.79,903.79 970.79,917.79 970.79,1020.79 991.25,1041.25 U7.23@991.26,1087.56
NetR102_1: R102.1 U9.8 U9.9 | length 201
  TOP w6: R102.1@263.41,2165.79 284.79,2165.79 296.61,2153.97 U9.9@347.58,2153.97 388.97,2153.97 395.3,2160.3 395.3,2170.4 386.14,2179.56 U9.8@347.58,2179.56
NetR103_2: R103.2 R106.2 U9.10 | length 139.4
  TOP w6: R106.2@263.41,2065.79 R103.2@263.41,2115.79 289.79,2115.79 302.38,2128.38 U9.10@347.58,2128.38
NetR104_2: R104.2 R107.2 U9.5 | length 145.2
  TOP w6: U9.5@571.99,2128.38 663.57,2128.38 R104.2@666.17,2125.79 R107.2@666.17,2075.79
NetR105_1: R105.1 U9.6 U9.7 | length 206.6
  TOP w6: U9.6@571.99,2153.97 531.61,2153.97 524.79,2160.79 524.79,2170.79 533.56,2179.56 U9.7@571.99,2179.56 662.39,2179.56 R105.1@666.17,2175.79
NetR110_1: R110.1 U9.1 U9.2 | length 170.7
  TOP w6: U9.2@571.99,2051.61 532.81,2051.61 527.9,2046.7 527.9,2031.3 533.18,2026.02 U9.1@571.99,2026.02 571.99,1972.2 R110.1@578.41,1965.79
NetR111_1: R111.1 U9.13 U9.14 | length 170.9
  TOP w6: R111.1@336.17,1965.79 336.17,1992.17 347.58,2003.58 U9.14@347.58,2026.02 385.52,2026.02 390.7,2031.2 390.7,2046.7 385.79,2051.61 U9.13@347.58,2051.61
NetR112_2: R112.2 R114.2 U9.3 | length 214.4
  TOP w6: U9.3@571.99,2077.2 613.01,2077.2 619.42,2070.79 619.42,2022.54 R112.2@666.17,1975.79 R114.2@666.17,1925.79
NetR113_2: R113.2 R115.2 U9.12 | length 166.1
  TOP w6: R115.2@263.41,1965.79 R113.2@263.41,2015.79 294.79,2047.17 294.79,2058.26 313.72,2077.2 U9.12@347.58,2077.2
NetR120_1: R120.1 R128.2 U10.B1 | length 127.2
  TOP w8: U10.B1@646.47,105.41 672.79,105.41 681.79,114.41 R128.2@718.17,114.41
  TOP w10: R120.1@718.17,62.62 R128.2@718.17,114.41
NetR121_1: R121.1 R127.2 U10.C1 | length 131.8
  TOP w8: R127.2@633.41,251.41 633.33,251.33 R121.1@633.33,202.14 633.33,173.87 646.47,160.72 U10.C1@646.47,125.09
NetR122_1: R122.1 R126.2 U11.1 | length 112.3
  TOP w8: R122.1@232.54,176.79 R126.2@281.79,176.79 281.79,171.51 284.7,168.6 U11.1@284.7,114.94
NetR125_1: R125.1 U11.5 | length 625.9
  TOP w6: U11.5@306.94,53.32 306.94,25.57 307.79,26.41 v1(307.79,27.41) ; v2(735.79,297.79) R125.1@735.79,353.79
  BOTTOM w6: v1(307.79,27.41) 465.41,27.41 v2(735.79,297.79)
NetR130_2: R130.2 U11.2 | length 140.6
  TOP w6: v1(182.79,101.79) R130.2@182.79,137.79 ; v1(257.79,101.79) 264.32,95.25 U11.2@284.7,95.25
  BOTTOM w6: v1(182.79,101.79) v1(257.79,101.79)
NetR132_1: R132.1 U11.11 | length 103.7
  TOP w8: U11.11@326.63,117.5 326.63,128.25 332.18,133.8 377.79,133.8 377.79,133.41 390.17,121.03 R132.1@411.79,121.03
NetR133_2: R133.2 U11.12 | length 69.6
  TOP w8: U11.12@306.94,117.5 306.94,132.57 331.79,157.41 R133.2@331.79,176.79
NetR134_2: R134.2 U10.B3 | length 77.1
  TOP w8: R134.2@537.41,87.41 563.79,87.41 581.79,105.41 U10.B3@607.1,105.41
NetR135_2: R135.2 U10.C3 | length 79.3
  TOP w8: R135.2@532.94,137.62 561.57,137.62 574.1,125.09 U10.C3@607.1,125.09
NetR138_2: R138.2 SW2.2 | length 121.1
  TOP w8: R138.2@-19.83,1719.79 -19.83,1828.75 SW2.2@-11.22,1837.36
NetR139_2: R139.2 SW3.2 | length 214.2
  TOP w8: R139.2@1912.41,2000.79 2079.37,2000.79 SW3.2@2112.8,2034.21
NetR144_2: R144.2 SW4.1 SW4.2 | length 313.9
  TOP w10: SW4.1@1985.86,2411.43 2037.79,2359.5 2037.79,2294.07 SW4.2@1985.86,2242.14 1985.86,2213.09 R144.2@2037.17,2161.79
NetR146_1: R146.1 U12.8 | length 227.1
  TOP w8: U12.8@1698.19,3568.32 1710.79,3580.91 ; 1710.79,3585.91 1710.79,3602.79
  TOP w15: 1710.79,3602.79 1710.79,3612.79 1724.79,3626.79 1810.79,3626.79 1837.79,3599.79 R146.1@1837.79,3561.41
P01_GPIO_10: J7.9 Q6.1 R59.1 R89.1 R123.1 R152.1 U7.1 | length 5662
  TOP w6: R89.1@25.17,850.79 25.17,874.47 31.49,880.79 v1(60.79,880.79) ; v1(79.79,1482.79) 92.79,1495.79 290.79,1495.79 312.6,1517.6 677.4,1517.6 736.21,1458.79 v1(787.79,1458.79) 838.15,1408.43 U7.1@847.56,1408.43 ; v1(345.79,632.79) 386.27,592.31 R123.1@429.54,592.31 ; v2(1059.79,2093.67) J7.9@1059.79,2165.59 ; v1(1109.79,1831.79) 1271.79,1831.79 1329.79,1889.79 1525.79,1889.79 1552,1863.57 1552,1697 1615.79,1633.21 1615.79,1588.79 1679.79,1524.79 1694.17,1524.79 R59.1@1717.17,1501.79 ; R152.1@1779.41,286.79 1794.19,272.01 Q6.1@1794.19,237.03 v1(1794.19,196.19)
  PWR w6: v1(79.79,1482.79) 79.79,1126.79 45.5,1092.5 45.5,896.07 v1(60.79,880.79) 60.79,754.21 132,683 295.57,683 v1(345.79,632.79)
  BOTTOM w6: v1(345.79,632.79) 375.57,603 616.57,603 675,544.57 675,485.57 848.07,312.5 848.36,312.79 1123.79,312.79 1172.47,264.1 1236.8,264.1 1259.11,241.79 1500.91,241.79 1513,229.7 1760.68,229.7 v1(1794.19,196.19) ; v1(787.79,1458.79) 787.79,1518.39 870.79,1601.39 870.79,1678.79 907.79,1715.79 993.79,1715.79 v1(1109.79,1831.79) 1109.79,2043.67 v2(1059.79,2093.67)
P02_GPIO_11: J7.11 Q4.1 R58.1 R91.1 R129.1 R151.1 U7.2 | length 5329
  TOP w6: v1(0.79,715.79) 0.79,732.29 19.29,750.79 R91.1@25.17,750.79 R91.1@30.17,750.79 ; v1(623.03,555.55) R129.1@623.03,593.31 ; v1(765.79,1425.79) 788.47,1425.79 825.52,1388.74 U7.2@847.56,1388.74 ; v2@1009.79,2091.15 v2(1009.79,2093.67) J7.11@1009.79,2165.59 ; v1(1055.79,1815.79) 1101.79,1861.79 1273.79,1861.79 1318.79,1906.79 1538.79,1906.79 1570,1875.57 1570,1808 1612.21,1765.79 1651.17,1765.79 R58.1@1717.17,1699.79 ; R151.1@1626.41,282.79 1642.19,267.01 Q4.1@1642.19,237.03 v1(1642.19,196.19)
  PWR w6: v1(28.79,1289.79) 28.79,1151.79 0.79,1123.79 v1(0.79,715.79) 86.79,629.79 181.79,629.79 256.02,555.55 v1(623.03,555.55)
  BOTTOM w6: v1(28.79,1289.79) 49.79,1289.79 60.79,1300.79 457.79,1300.79 568.79,1411.79 751.79,1411.79 v1(765.79,1425.79) 765.79,1521.49 847.79,1603.49 847.79,1682.79 894.79,1729.79 969.79,1729.79 v1(1055.79,1815.79) 1055.79,1876.79 1009.79,1922.79 v2(1009.79,2093.67) ; v1(623.03,555.55) 647.79,530.8 647.79,424.79 706.79,365.79 742.79,365.79 839.79,268.79 1108.81,268.79 1158.7,218.9 1223.4,218.9 1246.11,196.19 v1(1642.19,196.19)
P03_GPIO_12: R71.1 U7.3 | length 946.5
  TOP w6: R71.1@25.17,1356.79 25.17,1376.57 49.39,1400.79 382.79,1400.79 480.79,1498.79 656.79,1498.79 753.79,1401.79 784.79,1401.79 817.52,1369.06 U7.3@847.56,1369.06
P04_GPIO_13: R67.1 R125.2 R141.1 SW2.1 U7.4 | length 3426.1
  TOP w6: 745.79,1385.79 780.79,1385.79 817.21,1349.37 U7.4@847.56,1349.37
  TOP w8: R141.1@-35.83,2120.79 -35.83,2066.32 156.79,1873.7 156.79,1770.79 -9.21,1604.79 -9.21,1499.79 25.17,1465.41 R67.1@25.17,1441.79 -7.1,1409.52 -7.1,1332.9 7.01,1318.79 v1(28.79,1318.79) 84.79,1318.79 102.79,1300.79 376.49,1300.79 520.8,1445.1 673.47,1445.1 732.79,1385.79 745.79,1385.79 ; v1(681.79,433.79) R125.2@735.79,433.79
  PWR w6: v1(28.79,1318.79) 49.1,1298.47 49.1,1143.7 16.9,1111.5 16.9,748.67 115.79,649.79 185.79,649.79 258.57,577 629.87,577 681.79,525.08 v1(681.79,433.79)
P05_GPIO_14: R83.1 U7.5 | length 1239.4
  TOP w6: R83.1@25.17,1050.79 19.81,1050.79 -29.1,1099.7 -29.1,1186.9 0.1,1216.1 61.2,1216.1 76.71,1200.59 395.09,1200.59 457.79,1263.29 457.79,1352.09 528.49,1422.79 644.49,1422.79 701.27,1366 780.57,1366 816.58,1330 U7.5@847.56,1330
P06_GPIO_15: R74.2 R97.2 U7.6 | length 2076.8
  TOP w6: v1(819.79,1310) U7.6@847.56,1310 ; v1(2000.79,1200.79) 2000.79,1214.79 2014.79,1228.79 2072.79,1228.79 2079.68,1221.89 2079.68,1200.79 2110.79,1200.79 2133.79,1177.79 2133.79,1069.79 2114.79,1050.79 R74.2@2084.41,1050.79
  BOTTOM w6: v1@820.79,1310.79 819.79,1309.79 819.79,1046.79 897.79,968.79 1047.79,968.79 1087.07,929.5 1207.07,929.5 1228.79,907.79 1595.79,907.79 1621.79,933.79 1708.79,933.79 1781.79,1006.79 1781.79,1061.59 1820.99,1100.79 1970.79,1100.79 2000.79,1130.79 v1(2000.79,1200.79)
P07_GPIO_16: R70.2 R99.2 U7.7 | length 2316.7
  TOP w6: v1(701.79,1337.79) 714,1350 760.57,1350 799.79,1310.79 799.79,1299.79 809.58,1290 828.07,1290 828.39,1290.32 U7.7@847.56,1290.32 ; R99.2@2079.68,1100.79 2079.68,1150.79 R70.2@2084.41,1150.79 v1@2110.79,1150.79
  BOTTOM w6: v1(701.79,1337.79) 670.79,1306.79 670.79,1184.79 745.79,1109.79 745.79,1005.5 930.5,820.79 1205.79,820.79 1221.79,804.79 1256.31,804.79 1279.31,827.79 1622.79,827.79 1665.79,870.79 1775.79,870.79 1805.89,900.89 2005.69,900.89 2112.79,1007.99 v1(2112.79,1150.79)
P08_GPIO_17: R62.2 U7.8 | length 2323.7
  TOP w6: v1(741.79,1326.79) 762.07,1326.79 785.79,1303.07 785.79,1291.79 806.95,1270.63 U7.8@847.56,1270.63 ; R62.2@2080.49,1450.79 v1(2107.87,1450.79)
  BOTTOM w6: v1(741.79,1326.79) 741.79,1273.79 800.79,1214.79 800.79,1025.79 930.79,895.79 1081.5,895.79 1100.5,914.79 1201.79,914.79 1229.79,886.79 1274.79,886.79 1293.79,867.79 1594.79,867.79 1641.79,914.79 1724.79,914.79 1805.79,995.79 2000.79,995.79 2082.48,1077.48 2082.48,1421.4 v1@2111.87,1450.79
P15_GPIO_22: R86.2 R142.1 SW3.1 U7.15 | length 3020.9
  TOP w6: v1(780.79,1055.79) 780.79,1081.79 831.84,1132.84 U7.15@847.56,1132.83
  TOP w8: v1(1655.79,890.79) 1637.79,872.79 1637.79,688.79 1664.79,661.79 2043.79,661.79 2077.41,695.41 R86.2@2077.41,749.78 v1(2117.79,749.78) ; SW3.1@2112.8,1837.36 2112.8,1788.78 2126.41,1775.17 R142.1@2126.41,1739.79 v1(2126.41,1707.79)
  BOTTOM w6: v1(780.79,1055.79) 780.79,1010.79 921.79,869.79 1241.79,869.79 1263.79,847.79 1612.79,847.79 v1(1655.79,890.79) ; v1(2117.79,749.78) 2169.79,801.78 2169.79,1664.41 v1(2126.41,1707.79)
P16_GPIO_23: R45.2 R81.1 R95.1 R124.1 | length 2203.6
  TOP w6: R45.2@20.17,920.79 16.29,920.79 -10.3,894.2 -10.3,829.6 18.4,800.9 25.05,800.9 R95.1@25.17,800.79 25.17,783.33 32.71,775.79 103.99,775.79 126.99,798.79 177.79,798.79 199.79,776.79 199.79,696.79 v1(255.79,640.79) ; v1(394.17,642.31) R124.1@429.54,642.31 ; v2(1705.79,820.79) 1705.79,839.41 R81.1@1717.17,850.79
  PWR w6: v1(255.79,640.79) 290.79,605.79 357.65,605.79 v1(394.17,642.31) 432.27,642.31 459.79,614.79 642.79,614.79 766.79,738.79 981.79,738.79 1064.79,821.79 1206.79,821.79 1242.79,857.79 1271.79,857.79 1308.79,820.79 v2(1705.79,820.79)
P16_JTAG_TDI: J3.4 J8.8 R45.1 U7.16 | length 3434.6
  TOP w6: R45.1@67.41,920.79 79.79,920.79 v1(96.79,903.79) ; v1(586.79,957.79) 602.79,973.79 731.19,973.79 800.79,1043.39 800.79,1078.79 835.15,1113.15 U7.16@847.56,1113.15 ; v1(894.79,2273.79) 965,2344 1031,2344 J3.4@1101.79,2414.79 ; v1(1339,2311) 1540,2311 J8.8@1584.79,2355.79
  PWR w6: v1(586.79,957.79) 499,1045.57 499,1449 538.79,1488.79 538.79,1568.79 507.79,1599.79 507.79,1731.79 595.79,1819.79 625.79,1819.79 669.79,1863.79 770.79,1863.79 894.79,1987.79 v1(894.79,2273.79)
  BOTTOM w6: v1(96.79,903.79) 96.79,970.79 124.79,998.79 278.79,998.79 324.79,1044.79 482.62,1044.79 569.62,957.79 v1(586.79,957.79) ; J3.4@1101.79,2414.79 1205.57,2311 v1(1339,2311)
P17_GPIO_24: R46.2 R61.1 R85.1 R96.1 R131.1 | length 3068.8
  TOP w6: R96.1@71.19,642.68 178.22,642.68 200.11,620.79 279.22,620.79 348.22,689.79 597.79,689.79 623.03,664.54 R131.1@623.03,643.31 660.79,643.31 678.79,661.31 v1(678.79,690.79) ; v1(435.79,947.79) R46.2@495.79,947.79 ; v1(1679.79,750.79) R85.1@1717.17,750.79 ; v1(1685.79,1450.79) R61.1@1717.17,1450.79
  PWR w6: v1(1679.79,750.79) 1739.79,810.79 1739.79,1396.79 v1(1685.79,1450.79)
  BOTTOM w6: v1(435.79,947.79) 471.79,947.79 548.79,870.79 548.79,820.79 v1(678.79,690.79) 711.79,690.79 727.79,706.79 905.79,706.79 958.66,653.92 958.66,641.5 974.37,625.79 1157.5,625.79 1282.5,750.79 v1(1679.79,750.79)
P17_JTAG_TDO: J3.2 J8.6 R46.1 U7.17 | length 2926.9
  TOP w6: R46.1@543.03,947.79 560.79,947.79 572.79,935.79 v1(608.79,935.79) 631.79,958.79 738.79,958.79 814.79,1034.79 814.79,1064.79 837.56,1087.56 U7.17@873.15,1087.56 ; v1(928.79,2275.79) 956,2303 1090,2303 J3.2@1201.79,2414.79 1327.57,2289 1568,2289 J8.6@1634.79,2355.79
  PWR w6: v1(608.79,935.79) 608.79,977.79 586.79,999.79 565.22,999.79 520,1045.01 520,1437 562.79,1479.79 562.79,1581.79 522.79,1621.79 522.79,1713.79 602.79,1793.79 640.79,1793.79 687.79,1840.79 779.79,1840.79 928.79,1989.79 v1(928.79,2275.79)
P18_GPIO_28: R60.2 R69.1 U7.18 | length 2025.8
  TOP w6: v1(845.79,1060.79) 885.79,1060.79 892.84,1067.84 U7.18@892.83,1087.56 ; v1(1635.79,1600.79) 1649.79,1586.79 1795.79,1586.79 1807.79,1598.79 2057.79,1598.79 2079.41,1577.17 R60.2@2079.41,1550.79 ; v1(1681.79,1184.79) 1715.79,1150.79 R69.1@1717.17,1150.79
  BOTTOM w6: v1(845.79,1060.79) 864.79,1079.79 1143.79,1079.79 1194.79,1130.79 1194.79,1174.79 1246.79,1226.79 1405.79,1226.79 1447.79,1184.79 v1(1681.79,1184.79) 1722.79,1225.79 1722.79,1487.61 1663.3,1547.1 1663.3,1573.27 v1(1635.79,1600.79)
P19_JTAG_TCK: J3.6 J8.4 R48.1 U7.19 | length 3707.2
  TOP w6: R48.1@544.41,898.79 v1(582.79,898.79) 608.79,898.79 651.79,941.79 742.79,941.79 836,1035 884.8,1035 912.52,1062.72 U7.19@912.52,1087.56
  PWR w6: v1(582.79,898.79) 580.79,896.79 397.79,896.79 326.1,968.47 326.1,1320.1 381.79,1375.79 381.79,1588.79 477.79,1684.79 477.79,1775.79 574.79,1872.79 574.79,1911.79 614.79,1951.79 756.79,1951.79 833.79,2028.79 833.79,2192.79 v1(860.79,2219.79)
  BOTTOM w6: v1(860.79,2219.79) 860.79,2273.79 J3.6@1001.79,2414.79 1049.79,2462.79 1376.79,2462.79 1399,2485 1785.8,2485 1841,2429.8 1841,2365.5 1790.2,2314.7 1725.87,2314.7 J8.4@1684.79,2355.79
P20_JTAG_TMS: J3.8 J8.2 U7.20 | length 3781.7
  TOP w6: v1(446.79,916.79) 446.79,884.21 490.21,840.79 581.79,840.79 667.79,926.79 749.79,926.79 843,1020 889.6,1020 932.21,1062.61 U7.20@932.2,1087.56
  PWR w6: v1(446.79,916.79) 407.79,916.79 340.1,984.47 340.1,1294.1 400.2,1354.2 400.2,1570.2 491.79,1661.79 491.79,1764.79 617.79,1890.79 763.79,1890.79 861.79,1988.79 861.79,2172.79 v1(873.79,2184.79)
  BOTTOM w6: J3.8@901.79,2414.79 829,2342 829,2210 854.21,2184.79 v1(873.79,2184.79) 1243.79,2184.79 1367,2308 1367,2405 1419.3,2457.3 1748.8,2457.3 1780.8,2425.3 1780.8,2370.1 1766.49,2355.79 J8.2@1734.79,2355.79
P21_GPIO_25: R52.2 R66.1 R78.2 | length 1158.7
  TOP w6: R52.2@1525.79,1189.41 1525.79,1196.79 1559.79,1230.79 v1(1578.79,1230.79) ; v1(1680.6,1257.6) 1686.97,1257.6 1693.79,1250.79 1721.89,1250.79 1721.89,1271.89 1727.79,1277.79 1797.79,1277.79 1820.79,1300.79 1975.79,1300.79 2016.79,1341.79 2136.79,1341.79 2163.79,1314.79 2163.79,991.79 2122.79,950.79 R78.2@2079.68,950.79
  BOTTOM w6: v1(1578.79,1230.79) 1653.79,1230.79 v1(1680.6,1257.6)
P29_GPIO_26: R54.1 U7.29 | length 1533.4
  TOP w6: v1(1070.79,1045.79) 1089.65,1045.79 1109.37,1065.5 U7.29@1109.37,1087.56 ; R54.1@1717.17,1650.79 1717.17,1625.51 1733.89,1608.79 v1(1766.79,1608.79)
  BOTTOM w6: v1(1070.79,1045.79) 1070.79,995.79 1095.79,970.79 1136.11,970.79 1161.5,945.4 1213.17,945.4 1233.79,924.79 1579.07,924.79 1610.07,955.79 1627.29,955.79 1794.79,1123.29 1794.79,1580.79 v1(1766.79,1608.79)
P30_GPIO_27: R55.1 U7.30 | length 1278.5
  TOP w6: v1(1104.94,1032.79) 1129.06,1056.91 U7.30@1129.06,1087.56 ; v1(1688.79,1550.79) R55.1@1717.17,1550.79
  PWR w6: v1(1675.79,1049.79) 1657,1068.57 1657,1519 v1(1688.79,1550.79)
  BOTTOM w6: v1(1104.94,1032.79) 1183.79,1032.79 1209.79,1006.79 1209.79,974.02 1231.02,952.79 1578.79,952.79 v1(1675.79,1049.79)
P45_GPIO_31: R42.2 R64.2 | length 820.4
  TOP w6: R42.2@1465.79,1615.41 1465.79,1617.79 1480.79,1632.79 1588.79,1632.79 1599.79,1621.79 1599.79,1574.79 1646.79,1527.79 1646.79,1458.79 1678.79,1426.79 1784.79,1426.79 1815.79,1395.79 1992.79,1395.79 1999.79,1402.79 2072.79,1402.79 2079.41,1396.17 R64.2@2079.41,1369.79
P50_GPIO_00: R92.2 R93.1 U7.50 | length 3018.8
  TOP w6: R92.2@364.41,749.79 673.79,749.79 v1(742.79,680.79) ; v1(1127.79,1599.79) 1137.79,1589.79 1137.79,1472.79 1148.74,1461.84 U7.50@1148.74,1434.02 ; v1(1606.4,1492.5) 1606.4,1464.1 1660.71,1409.79 1708.17,1409.79 R93.1@1717.17,1400.79 1694.17,1377.79 1678.19,1377.79 1618.79,1318.39 1618.79,718.79 v1(1615.79,715.79)
  BOTTOM w6: v1(742.79,680.79) 755.79,680.79 860.79,575.79 1202.79,575.79 1220.79,593.79 1220.79,617.79 1247.79,644.79 1585.79,644.79 1615.79,674.79 v1(1615.79,715.79) ; v1(1127.79,1599.79) 1170.79,1556.79 1504.79,1556.79 1541.07,1520.5 1578.4,1520.5 v1(1606.4,1492.5)
P53_GPIO_30: R88.2 U7.53 | length 1860.7
  TOP w6: R88.2@361.41,949.79 485.2,826 597,826 v1(659.79,888.79) ; v1(969.79,1633.79) 975.41,1628.17 1021.17,1628.17 1028.79,1635.79 1061.31,1635.79 1077.79,1619.31 1077.79,1537.79 1089.69,1525.89 U7.53@1089.68,1434.02
  PWR w6: v1(659.79,888.79) 659.79,1075.29 716.79,1132.29 716.79,1233.79 689,1261.57 689,1319.7 681.79,1326.91 681.79,1537.79 795,1651 795,1735 815.79,1755.79 863.79,1755.79 969.79,1649.79 v1(969.79,1633.79)
P55_GPIO_01: J5.2 R34.1 U7.55 | length 1373.8
  TOP w6: J5.2@701.79,2514.79 651.79,2464.79 651.79,2351.79 674.37,2329.2 762.6,2329.2 839,2252.8 839,1898 894.71,1842.29 R34.1@942.79,1842.29 942.79,1628.79 961.42,1610.16 1008.15,1610.16 1024.79,1593.52 1024.79,1508.79 1040.79,1492.79 1040.79,1473.05 1046.63,1467.21 1046.63,1466.95 1050.32,1463.26 U7.55@1050.31,1434.02
P57_GPIO_02: J6.2 R33.1 U7.57 | length 1534.6
  TOP w6: J6.2@601.79,2514.79 551.79,2464.79 551.79,2364.51 614.5,2301.8 762.5,2301.8 822.79,2241.51 822.79,1845.79 v1(913.79,1754.79) 926.79,1741.79 926.79,1537.5 1010.95,1453.34 U7.57@1010.94,1434.02 ; v1(1009.79,1803.11) R33.1@1009.79,1843.29
  BOTTOM w6: v1(913.79,1754.79) 962.11,1803.11 v1(1009.79,1803.11)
